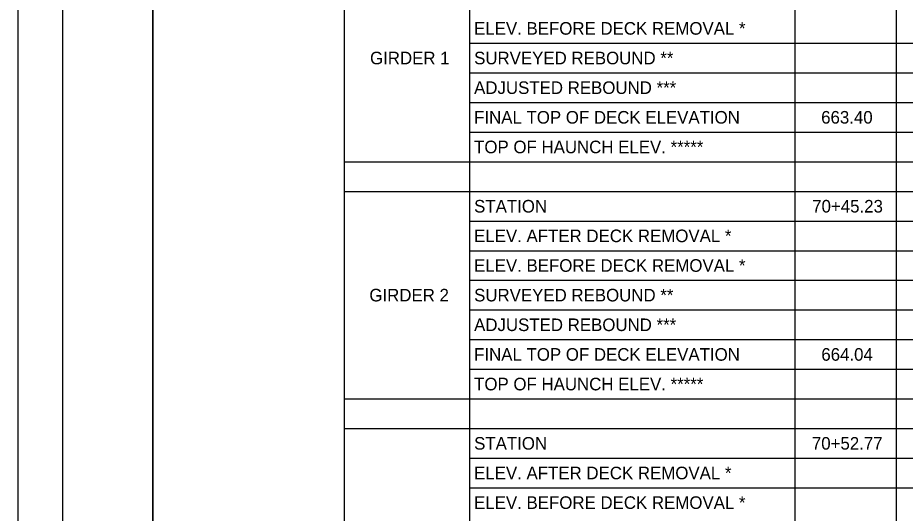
# Model space of a CAD drawing. Extents: x 0 to 34, y 0 to 22.
# Drawn here: x 0 to 9.87, y 11.03 to 16.55 of the extents above; entities that cross this region are included whole.
import ezdxf

# ---------------------------------------------------------------- set-up
doc = ezdxf.new("R2010")
doc.units = 0
for name, color, linetype in [('SH_Border', 7, 'Continuous'), ('SH_Cut_Line', 7, 'Continuous'), ('SH_Text', 7, 'Continuous')]:
    doc.layers.add(name, color=color, linetype=linetype)

msp = doc.modelspace()

# ---------------------------------------------------------------- linework, layer by layer
at = {"layer": 'SH_Border'}
for points in [[(0.5, 21.5), (1.5, 21.5), (1.5, 0.5), (0.5, 0.5)], [(1.5, 21.5), (33.5, 21.5), (33.5, 0.5), (1.5, 0.5)]]:
    msp.add_lwpolyline(points, close=True, dxfattribs=at)
at = {"layer": 'SH_Cut_Line'}
msp.add_lwpolyline([(0, 0), (34, 0), (34, 22), (0, 22)], close=True, dxfattribs=at)
at = {"layer": 'SH_Text'}
for p, q in [((3.6273, 20.5877), (3.6273, 1.7561)), ((5.0222, 20.0804), (5.0222, 1.7561)), ((8.6364, 20.0804), (8.6364, 1.7561)), ((9.765, 19.4083), (9.765, 1.7561)), ((5.0222, 16.2634), (20.0494, 16.2634)), ((5.0222, 15.9337), (20.0494, 15.9337)), ((5.0222, 15.604), (20.0494, 15.604)), ((5.0222, 15.2743), (20.0494, 15.2743)), ((3.6273, 14.9445), (20.0494, 14.9445)), ((3.6273, 14.6148), (20.0494, 14.6148)), ((5.0222, 14.2851), (20.0494, 14.2851)), ((5.0222, 13.9554), (20.0494, 13.9554)), ((5.0222, 13.6257), (20.0494, 13.6257)), ((5.0222, 13.296), (20.0494, 13.296)), ((5.0222, 12.9663), (20.0494, 12.9663)), ((5.0222, 12.6366), (20.0494, 12.6366)), ((3.6273, 12.3069), (20.0494, 12.3069)), ((3.6273, 11.9772), (20.0494, 11.9772)), ((5.0222, 11.6474), (20.0494, 11.6474)), ((5.0222, 11.3177), (20.0494, 11.3177))]:
    msp.add_line(p, q, dxfattribs=at)

# ---------------------------------------------------------------- texts
for s, p in [('ELEV. BEFORE DECK REMOVAL *', (5.0729, 16.3582)), ('GIRDER 1', (3.9158, 16.0285)), ('SURVEYED REBOUND **', (5.0729, 16.0285)), ('ADJUSTED REBOUND ***', (5.0729, 15.6988)), ('FINAL TOP OF DECK ELEVATION', (5.0729, 15.3691)), ('663.40', (8.9308, 15.3691)), ('TOP OF HAUNCH ELEV. *****', (5.0729, 15.0394)), ('STATION', (5.0729, 14.38)), ('70+45.23', (8.8312, 14.38)), ('ELEV. AFTER DECK REMOVAL *', (5.0729, 14.0503)), ('ELEV. BEFORE DECK REMOVAL *', (5.0729, 13.7206)), ('GIRDER 2', (3.9085, 13.3909)), ('SURVEYED REBOUND **', (5.0729, 13.3909)), ('ADJUSTED REBOUND ***', (5.0729, 13.0611)), ('FINAL TOP OF DECK ELEVATION', (5.0729, 12.7314)), ('664.04', (8.9326, 12.7314)), ('TOP OF HAUNCH ELEV. *****', (5.0729, 12.4017)), ('STATION', (5.0729, 11.7423)), ('70+52.77', (8.8278, 11.7423)), ('ELEV. AFTER DECK REMOVAL *', (5.0729, 11.4126)), ('ELEV. BEFORE DECK REMOVAL *', (5.0729, 11.0829))]:
    msp.add_text(s, height=0.14, dxfattribs=at).set_placement(p)

doc.saveas('drawing.dxf')
